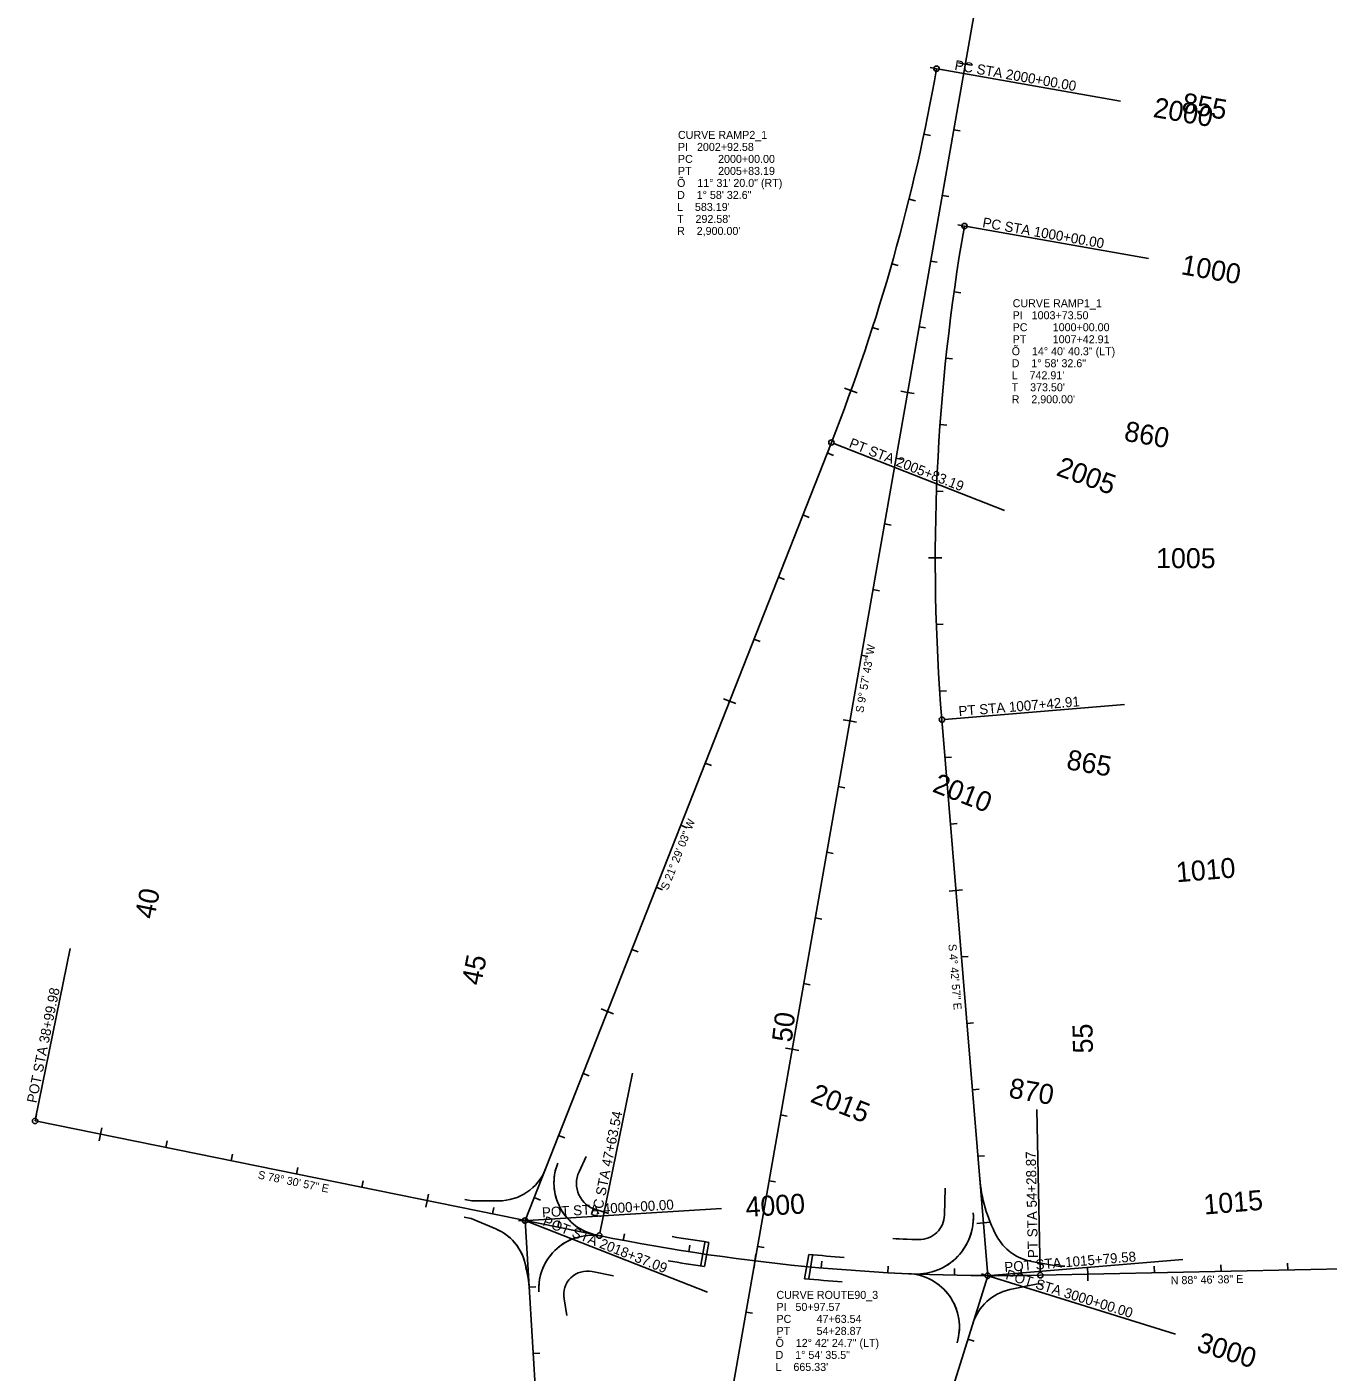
# Model space of a CAD drawing. Extents: x 2819977 to 2827606, y 116785 to 150320.
# Drawn here: x 2819977 to 2821928, y 131991 to 134009 of the extents above; entities that cross this region are included whole.
import ezdxf

# ---------------------------------------------------------------- set-up
doc = ezdxf.new("R2010")
doc.units = 0
for name, color, linetype in [('Default', 7, 'Continuous'), ('Modeling-Contours-Minor-Existing', 7, 'Continuous'), ('Modeling-Flow Arrows-Existing', 7, 'Continuous'), ('Modeling-Spot-Existing', 7, 'Continuous'), ('Modeling-Triangle Verticies-Existing', 7, 'Continuous'), ('Modeling-Triangles-Existing', 7, 'Continuous'), ('Roadway-Safety', 7, 'Continuous'), ('Roadway-Walls', 7, 'Continuous'), ('Scratch-5', 7, 'Continuous')]:
    doc.layers.add(name, color=color, linetype=linetype)

msp = doc.modelspace()

# ---------------------------------------------------------------- linework, layer by layer
at = {"layer": 'Default'}
for p, q in [((2821447.5, 134317.2), (2821007.1, 131809.7)), ((2821182.9, 133385.4), (2820723.6, 132218.6)), ((2821348.6, 132969.8), (2821417.3, 132135.9)), ((2821496.2, 132136.6), (2822062.3, 132148.7))]:
    msp.add_line(p, q, dxfattribs=at)
for points in [[(2820633.3, 132250.2), (2820643.5, 132248.2), (2820683.9, 132248.1)], [(2820632.4, 132223.8), (2820642.5, 132221.7), (2820679.8, 132206.1)], [(2821483, 132157.3), (2821522.9, 132150.2), (2821533.1, 132150.4)], [(2821500.4, 132123.7), (2821490.2, 132123.4), (2821450.3, 132115)]]:
    msp.add_lwpolyline(points, dxfattribs=at)
for centre, radius, start, end in [((2820684.2, 132323.1), 75, 269.8258, 338.5158), ((2820846.9, 132275.2), 80, 158.5158, 258.5158), ((2820846.9, 132275.2), 80, 158.5158, 226.7275), ((2821629.5, 132300.5), 225, 184.7159, 207.699), ((2821310.8, 132223.4), 85, 267.6126, 4.7159), ((2821310.8, 132223.4), 85, 298.8531, 4.7159), ((2820650.7, 132136.9), 75, 5.6638, 67.2052), ((2820650.7, 132136.9), 75, 14.5264, 67.2052), ((2820824.1, 132116.5), 80, 78.6123, 183.5158), ((2820824.1, 132116.5), 80, 110.3101, 183.5158), ((2821432.2, 135135.9), 3000, 258.5158, 271.2227), ((2821496.5, 132231.1), 75, 208.01, 260.1013), ((2820505.5, 132099.3), 225, 3.5158, 14.5264), ((2821294.9, 132059), 80, 342.7159, 87.4455), ((2821294.9, 132059), 80, 342.7159, 56.0514), ((2821466.6, 132041.8), 75, 102.5617, 162.7159)]:
    msp.add_arc(centre, radius, start, end, dxfattribs=at)
at = {"layer": 'Modeling-Flow Arrows-Existing'}
for p, q in [((2821447.5, 134317.2), (2821007.1, 131809.7)), ((2821340.6, 133945.8), (2821330.8, 133947.5)), ((2821340.6, 133945.8), (2821350.5, 133944)), ((2821383.5, 133952.8), (2821373.7, 133954.5)), ((2821383.5, 133952.8), (2821393.3, 133951.1)), ((2821321.6, 133847.6), (2821331.4, 133845.5)), ((2821366.2, 133854.3), (2821376.1, 133852.6)), ((2821299.3, 133750.1), (2821309, 133747.7)), ((2821348.9, 133755.8), (2821358.8, 133754.1)), ((2821382.5, 133709.9), (2821372.6, 133711.6)), ((2821382.5, 133709.9), (2821392.3, 133708.2)), ((2821273.6, 133653.5), (2821283.2, 133650.8)), ((2821331.6, 133657.3), (2821341.5, 133655.6)), ((2821366.9, 133611.1), (2821376.8, 133609.7)), ((2821244.5, 133557.8), (2821254.1, 133554.8)), ((2821314.3, 133558.8), (2821324.2, 133557.1)), ((2821354.7, 133511.9), (2821364.6, 133510.8)), ((2821212.2, 133463.2), (2821202.8, 133466.6)), ((2821212.2, 133463.2), (2821221.6, 133459.8)), ((2821297, 133460.3), (2821287.2, 133462.1)), ((2821297, 133460.3), (2821306.9, 133458.6)), ((2821345.9, 133412.3), (2821355.9, 133411.5)), ((2821182.9, 133385.4), (2820723.6, 132218.6)), ((2821176.7, 133369.7), (2821186, 133366.1)), ((2821279.7, 133361.8), (2821289.6, 133360.1)), ((2821340.6, 133312.4), (2821350.6, 133312)), ((2821140.1, 133276.7), (2821149.4, 133273)), ((2821262.4, 133263.3), (2821272.3, 133261.6)), ((2821338.7, 133212.4), (2821328.7, 133212.4)), ((2821338.7, 133212.4), (2821348.7, 133212.4)), ((2821103.5, 133183.6), (2821112.8, 133179.9)), ((2821245.1, 133164.8), (2821255, 133163.1)), ((2821340.3, 133112.4), (2821350.3, 133112.8)), ((2821066.8, 133090.6), (2821076.1, 133086.9)), ((2821227.8, 133066.4), (2821237.7, 133064.6)), ((2821030.2, 132997.5), (2821020.9, 133001.2)), ((2821030.2, 132997.5), (2821039.5, 132993.8)), ((2821345.3, 133012.6), (2821355.3, 133013.2)), ((2821210.5, 132967.9), (2821200.7, 132969.6)), ((2821210.5, 132967.9), (2821220.4, 132966.1)), ((2821348.6, 132969.8), (2821417.3, 132135.9)), ((2820993.6, 132904.5), (2821002.9, 132900.8)), ((2821353.3, 132912.9), (2821363.2, 132913.7)), ((2821193.2, 132869.4), (2821203.1, 132867.6)), ((2820957, 132811.4), (2820966.3, 132807.7)), ((2821361.5, 132813.2), (2821371.4, 132814)), ((2821175.9, 132770.9), (2821185.8, 132769.2)), ((2820920.3, 132718.4), (2820929.6, 132714.7)), ((2821369.7, 132713.6), (2821379.7, 132714.4)), ((2821369.7, 132713.6), (2821359.7, 132712.7)), ((2821158.6, 132672.4), (2821168.5, 132670.7)), ((2820883.7, 132625.3), (2820893, 132621.6)), ((2821377.9, 132613.9), (2821387.9, 132614.7)), ((2821141.3, 132573.9), (2821151.2, 132572.2)), ((2820847.1, 132532.2), (2820837.8, 132535.9)), ((2820847.1, 132532.2), (2820856.4, 132528.6)), ((2821386.1, 132514.2), (2821396.1, 132515.1)), ((2821124, 132475.4), (2821114.2, 132477.1)), ((2821124, 132475.4), (2821133.9, 132473.7)), ((2820810.5, 132439.2), (2820819.8, 132435.5)), ((2821394.4, 132414.6), (2821404.3, 132415.4)), ((2819988.7, 132367.9), (2819990.7, 132377.7)), ((2821106.7, 132376.9), (2821116.6, 132375.2)), ((2819988.7, 132367.9), (2820834.9, 132196)), ((2820086.7, 132348), (2820088.7, 132357.8)), ((2820086.7, 132348), (2820084.7, 132338.2)), ((2820184.7, 132328.1), (2820186.7, 132337.9)), ((2820773.8, 132346.1), (2820783.2, 132342.5)), ((2820282.7, 132308.2), (2820284.7, 132318)), ((2821402.6, 132314.9), (2821412.5, 132315.7)), ((2820380.7, 132288.3), (2820382.7, 132298.1)), ((2820478.7, 132268.3), (2820480.7, 132278.1)), ((2821089.4, 132278.4), (2821099.3, 132276.7)), ((2820576.7, 132248.4), (2820578.7, 132258.2)), ((2820737.2, 132253.1), (2820746.5, 132249.4)), ((2820576.7, 132248.4), (2820574.7, 132238.6)), ((2820674.7, 132228.5), (2820676.7, 132238.3)), ((2820723.6, 132218.6), (2820713.7, 132218)), ((2820723.6, 132218.6), (2820733.6, 132219.2)), ((2820723.6, 132218.6), (2820799.5, 130984.2)), ((2820772.7, 132208.6), (2820774.7, 132218.4)), ((2821410.8, 132215.3), (2821400.8, 132214.4)), ((2821410.8, 132215.3), (2821420.8, 132216.1)), ((2820870.7, 132188.9), (2820872.6, 132198.7)), ((2820969.2, 132171.8), (2820970.8, 132181.7)), ((2821072.1, 132179.9), (2821082, 132178.2)), ((2821068.3, 132158.1), (2821067.1, 132148.1)), ((2821068.3, 132158.1), (2821069.5, 132168)), ((2821167.7, 132147.6), (2821168.6, 132157.5)), ((2821267.5, 132140.4), (2821268, 132150.4)), ((2821667.3, 132140.2), (2821667.1, 132150.2)), ((2821767.3, 132142.4), (2821767.1, 132152.4)), ((2821867.3, 132144.5), (2821867.1, 132154.5)), ((2821417.3, 132135.9), (2821006.7, 130816.2)), ((2821367.4, 132136.6), (2821367.6, 132146.6)), ((2821417.3, 132135.9), (2821407.8, 132138.9)), ((2821417.3, 132135.9), (2821426.9, 132133)), ((2821467.4, 132136.1), (2821467.3, 132146.1)), ((2821496.2, 132136.6), (2822062.3, 132148.7)), ((2821567.4, 132138.1), (2821567.1, 132148.1)), ((2821567.4, 132138.1), (2821567.6, 132128.1)), ((2820729.8, 132118.8), (2820739.7, 132119.4)), ((2821054.8, 132081.4), (2821064.7, 132079.7)), ((2821387.6, 132040.5), (2821397.2, 132037.5)), ((2820735.9, 132019), (2820745.9, 132019.6))]:
    msp.add_line(p, q, dxfattribs=at)
for centre, radius, start, end in [((2818484.4, 134447.5), 2900, 338.5158, 350.0381), ((2824238.7, 133208.2), 2900, 170.0381, 184.7159), ((2821432.2, 135135.9), 3000, 258.5158, 271.2227)]:
    msp.add_arc(centre, radius, start, end, dxfattribs=at)
at = {"layer": 'Modeling-Spot-Existing'}
for p, q in [((2821344.6, 133945.1), (2821616.4, 133897.4)), ((2821386.4, 133709.2), (2821658.2, 133661.5)), ((2821186.6, 133383.9), (2821442.3, 133283.3)), ((2821352.5, 132970.1), (2821622.6, 132992.4)), ((2819989.5, 132371.8), (2820041.2, 132626.4)), ((2820835.7, 132199.9), (2820884.5, 132439.7)), ((2821496.1, 132140.6), (2821490.9, 132385.3)), ((2820727.6, 132218.8), (2821018, 132236.7)), ((2820727.4, 132217.1), (2820997, 132111)), ((2821421.3, 132136.3), (2821710.1, 132160.1)), ((2821421.2, 132134.8), (2821699, 132048.3))]:
    msp.add_line(p, q, dxfattribs=at)
for centre in [(2821340.6, 133945.8), (2821382.5, 133709.9), (2821182.9, 133385.4), (2821348.6, 132969.8), (2819988.7, 132367.9), (2820723.6, 132218.6), (2820723.6, 132218.6), (2820834.9, 132196), (2821417.3, 132135.9), (2821417.3, 132135.9), (2821496.2, 132136.6)]:
    msp.add_circle(centre, 4, dxfattribs=at)
at = {"layer": 'Modeling-Triangles-Existing'}
msp.add_line((2821352.5, 132226.9), (2821353.4, 132267.2), dxfattribs=at)
msp.add_lwpolyline([(2821274.9, 132191.6), (2821279.8, 132191.4), (2821284.7, 132191.1), (2821290.6, 132190.8), (2821296.4, 132190.5), (2821303.7, 132190.4), (2821310.9, 132190.2), (2821314, 132190.1)], dxfattribs=at)
msp.add_arc((2821314.9, 132227.7), 37.6, 268.649, 358.7397, dxfattribs=at)
at = {"layer": 'Roadway-Safety'}
for p, q in [((2820987, 132151.6), (2820993, 132185.8)), ((2821154.7, 132166.2), (2821148.9, 132131.9))]:
    msp.add_line(p, q, dxfattribs=at)
at = {"layer": 'Roadway-Walls'}
for p, q in [((2820804.5, 132291.9), (2820815.2, 132314.7)), ((2820992.7, 132149.6), (2820999.1, 132185.9)), ((2821149, 132167.8), (2821142.6, 132131.4)), ((2820824, 132142.2), (2820856.2, 132135.8)), ((2820782, 132101.3), (2820786.4, 132076.2))]:
    msp.add_line(p, q, dxfattribs=at)
msp.add_lwpolyline([(2820831.2, 132234.5), (2820831.3, 132234.5), (2820848.9, 132229.3)], dxfattribs=at)
for centre, radius, start, end in [((2820841.6, 132274.3), 41.1, 154.6527, 255.3264), ((2821432.2, 135135.9), 2981.6, 260.5778, 261.6477), ((2821432.2, 135135.9), 3018.4, 260.5778, 261.628), ((2821432.2, 135135.9), 2981.6, 264.5489, 265.5721), ((2820817.1, 132107.4), 35.5, 78.7033, 189.8149), ((2821432.2, 135135.9), 3018.4, 264.4939, 265.5721)]:
    msp.add_arc(centre, radius, start, end, dxfattribs=at)
at = {"layer": 'Scratch-5'}
for p, q in [((2820804.5, 132291.9), (2820815.2, 132314.7)), ((2821352.5, 132226.9), (2821353.4, 132267.2)), ((2820856.2, 132135.8), (2820824, 132142.2)), ((2820782, 132101.3), (2820786.4, 132076.2))]:
    msp.add_line(p, q, dxfattribs=at)
for points in [[(2820848.9, 132229.3), (2820831.3, 132234.5), (2820831.2, 132234.5)], [(2821274.9, 132191.6), (2821279.8, 132191.4), (2821284.7, 132191.1), (2821290.6, 132190.8), (2821296.4, 132190.5), (2821303.7, 132190.4), (2821310.9, 132190.2), (2821314, 132190.1)]]:
    msp.add_lwpolyline(points, dxfattribs=at)
for centre, radius, start, end in [((2820841.6, 132274.3), 41.1, 154.6527, 255.3264), ((2821314.9, 132227.7), 37.6, 268.649, 358.7397), ((2820817.1, 132107.4), 35.5, 78.7033, 189.8149)]:
    msp.add_arc(centre, radius, start, end, dxfattribs=at)

# ---------------------------------------------------------------- texts
at = {"layer": 'Modeling-Contours-Minor-Existing'}
for s, rotation, p in [('S 9%%d 57\' 43" W', 80.0381, (2821230.8, 132979.3)), ('S 21%%d 29\' 03" W', 68.5158, (2820937.7, 132713.2)), ('S 4%%d 42\' 57" E', 274.7159, (2821358.3, 132632.9)), ('S 78%%d 30\' 57" E', 348.5158, (2820322.2, 132281.8)), ('N 88%%d 46\' 38" E', 1.2227, (2821691.9, 132122.8))]:
    msp.add_text(s, height=12, rotation=rotation, dxfattribs=at).set_placement(p)
at = {"layer": 'Modeling-Flow Arrows-Existing'}
for s, rotation, p in [(' 855', 350.0381, (2821696.1, 133882.7)), (' 2000', 350.0381, (2821653.2, 133875.6)), (' 1000', 350.0381, (2821695, 133639.8)), (' 860', 350.0381, (2821609.6, 133390.2)), (' 2005', 340.1595, (2821508.1, 133340.5)), (' 1005', 359.9166, (2821658.7, 133197)), (' 865', 350.0381, (2821523.1, 132897.7)), (' 2010', 338.5158, (2821322.5, 132866.4)), (' 1010', 4.7159, (2821689.8, 132724.9)), (' 40', 78.5158, (2820165.1, 132658.6)), (' 45', 78.5158, (2820655.1, 132559)), (' 50', 83.0319, (2821122, 132473.9)), (' 55', 91.2227, (2821575.5, 132458.4)), (' 870', 350.0381, (2821436.6, 132405.3)), (' 2015', 338.5158, (2821139.4, 132401.1)), (' 4000', 3.5158, (2821044, 132223.2)), (' 1015', 4.7159, (2821731, 132226.6)), (' 3000', 342.7159, (2821718.4, 132026.5))]:
    msp.add_text(s, height=30, rotation=rotation, dxfattribs=at).set_placement(p)
at = {"layer": 'Modeling-Spot-Existing'}
for s, rotation, p in [('PC STA 2000+00.00', 350.0381, (2821366.8, 133944.2)), ('PC STA 1000+00.00', 350.0381, (2821408.6, 133708.3)), ('PT STA 2005+83.19', 338.5158, (2821208.2, 133378.6)), ('PT STA 1007+42.91', 4.7159, (2821374.2, 132974.9)), ('POT STA 38+99.98', 78.5158, (2819990.9, 132394)), ('PC STA 47+63.54', 78.5158, (2820837.2, 132222)), ('PT STA 54+28.87', 91.2227, (2821492.7, 132162.5)), ('POT STA 4000+00.00', 3.5158, (2820749.4, 132223.2)), ('POT STA 2018+37.09', 338.5158, (2820748.9, 132211.8)), ('POT STA 1015+79.58', 4.7159, (2821443, 132141.1)), ('POT STA 3000+00.00', 342.7159, (2821443.1, 132131.1))]:
    msp.add_text(s, height=15, rotation=rotation, dxfattribs=at).set_placement(p)
at = {"layer": 'Modeling-Triangle Verticies-Existing'}
for s, p in [('CURVE RAMP2_1', (2820952.8, 133840.6)), ('PI   2002+92.58', (2820952.8, 133822.6)), ('PC', (2820952.8, 133804.6)), ('2000+00.00', (2821013, 133804.6)), ('Õ    11%%d 31\' 20.0" (RT)', (2820951.5, 133768.6)), ('PT', (2820952.8, 133786.6)), ('2005+83.19', (2821013, 133786.6)), ('D    1%%d 58\' 32.6"', (2820951.5, 133750.6)), ("L    583.19'", (2820951.5, 133732.6)), ("T    292.58'", (2820951.5, 133714.6)), ("R    2,900.00'", (2820951.5, 133696.6)), ('CURVE RAMP1_1', (2821454.7, 133588.2)), ('PI   1003+73.50', (2821454.7, 133570.2)), ('PC', (2821454.7, 133552.2)), ('1000+00.00', (2821514.8, 133552.2)), ('PT', (2821454.7, 133534.2)), ('1007+42.91', (2821514.8, 133534.2)), ('Õ    14%%d 40\' 40.3" (LT)', (2821453.3, 133516.2)), ('D    1%%d 58\' 32.6"', (2821453.3, 133498.2)), ("L    742.91'", (2821453.3, 133480.2)), ("T    373.50'", (2821453.3, 133462.2)), ("R    2,900.00'", (2821453.3, 133444.2)), ('CURVE ROUTE90_3', (2821100.5, 132101.1)), ('PI   50+97.57', (2821100.5, 132083.1)), ('PC', (2821100.5, 132065.1)), ('47+63.54', (2821160.7, 132065.1)), ('PT', (2821100.5, 132047.1)), ('54+28.87', (2821160.7, 132047.1)), ('Õ    12%%d 42\' 24.7" (LT)', (2821099.2, 132029.1)), ('D    1%%d 54\' 35.5"', (2821099.2, 132011.1)), ("L    665.33'", (2821099.2, 131993.1))]:
    msp.add_text(s, height=12, dxfattribs=at).set_placement(p)

doc.saveas('drawing.dxf')
